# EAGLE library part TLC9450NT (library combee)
TI TLC5940 16 Channel LED Driver
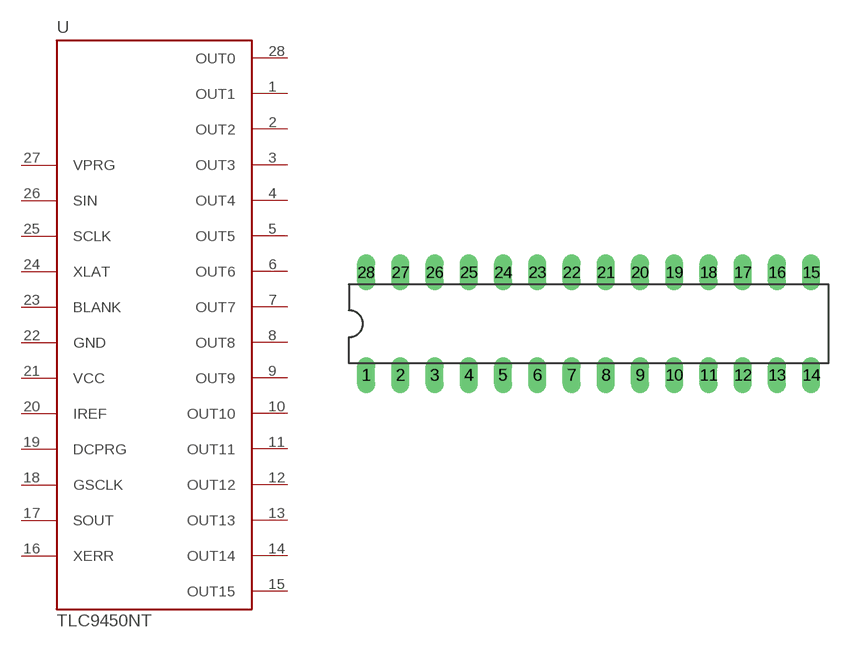
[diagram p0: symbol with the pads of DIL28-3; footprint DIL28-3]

Designator prefix -

## TLC9450NT  [DIL28-3]
1  OUT1
2  OUT2
3  OUT3
4  OUT4
5  OUT5
6  OUT6
7  OUT7
8  OUT8
9  OUT9
10  OUT10
11  OUT11
12  OUT12
13  OUT13
14  OUT14
15  OUT15
16  XERR
17  SOUT
18  GSCLK
19  DCPRG
20  IREF
21  VCC
22  GND
23  BLANK
24  XLAT
25  SCLK
26  SIN
27  VPRG
28  OUT0

## Footprint DIL28-3 (pad centres in mm)
Dual In Line Package Small
drill 0.813 long: 1 -16.51,-3.81; 2 -13.97,-3.81; 3 -11.43,-3.81; 4 -8.89,-3.81; 5 -6.35,-3.81; 6 -3.81,-3.81; 7 -1.27,-3.81; 8 1.27,-3.81; 9 3.81,-3.81; 10 6.35,-3.81; 11 8.89,-3.81; 12 11.43,-3.81; 13 13.97,-3.81; 14 16.51,-3.81; 15 16.51,3.81; 16 13.97,3.81; 17 11.43,3.81; 18 8.89,3.81; 19 6.35,3.81; 20 3.81,3.81; 21 1.27,3.81; 22 -1.27,3.81; 23 -3.81,3.81; 24 -6.35,3.81; 25 -8.89,3.81; 26 -11.43,3.81; 27 -13.97,3.81; 28 -16.51,3.81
